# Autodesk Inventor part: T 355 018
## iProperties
Company: Mayer & Müller AG Schaltgeräte
Created: 2005-12
Part Number: T 355 018
Material: 1.4301
Description: Bolzen
Document SubType Name: Modeling
Designer: I.Baliuc
Manufacturer: Standard
Standards Organization: Custom
Density: 7.86 g/cm^3
HalbzeugNorm: DIN 671
Zweck: Strombahn 1600 / 2000
Abmessung: Rd 8 - 95,4
Author: T.Messerschmitt
Revision Number: 355018
Comments: Werkstoff geändert von 2.0402.30 auf 1.4301 - am 28.04.2006 Hr.Klaes
Keywords: 266137
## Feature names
1. Extrusion2
